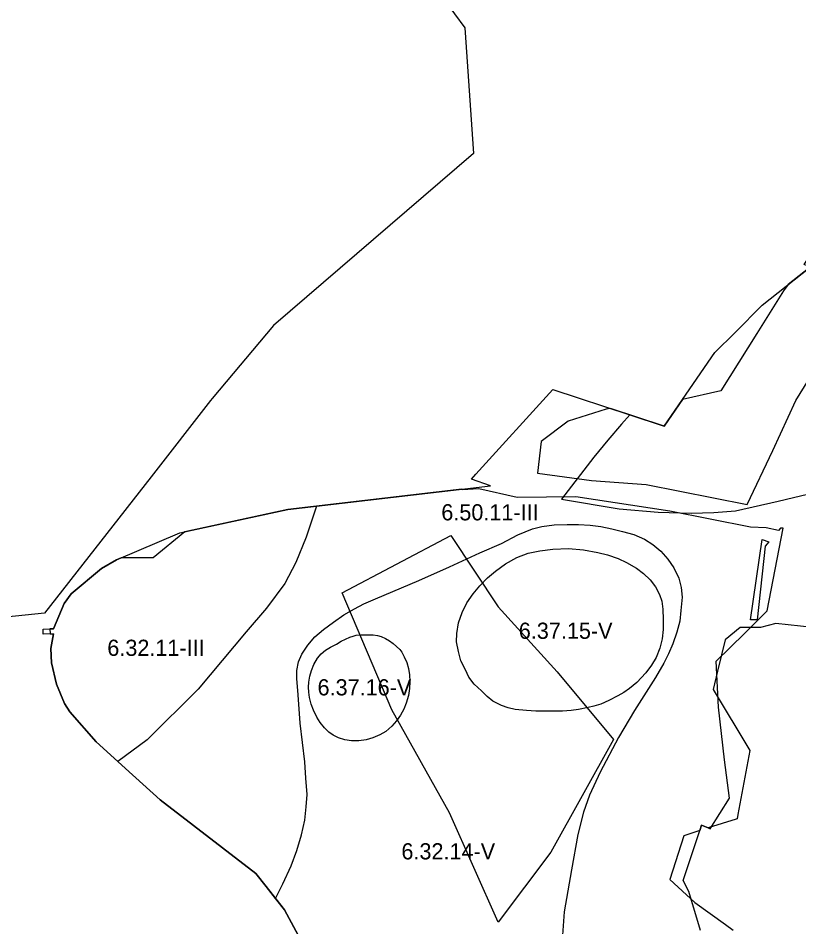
# Model space of a CAD drawing. Extents: x -555156 to -540209, y -1046851 to -1035695.
# Drawn here: x -545128 to -544645, y -1043130 to -1042568 of the extents above; entities that cross this region are included whole.
import ezdxf

# ---------------------------------------------------------------- set-up
doc = ezdxf.new("R2010")
doc.units = 0
for name, color, linetype in [('Vrstva 27', 7, 'Continuous'), ('Vrstva 28', 7, 'Continuous'), ('Vrstva 29', 7, 'Continuous')]:
    doc.layers.add(name, color=color, linetype=linetype)

msp = doc.modelspace()

# ---------------------------------------------------------------- linework, layer by layer
at = {"layer": 'Vrstva 28'}
for points in [[(-544870.74, -1042547.47), (-544851.56, -1042573.64), (-544846.21, -1042651.41), (-544969.84, -1042757.77), (-545007.86, -1042802.87), (-545008.88, -1042804.18), (-545045.53, -1042851.36), (-545111.56, -1042935.6), (-545207.45, -1042945.54)], [(-544749.41, -1042812.98), (-544728.08, -1042820), (-544696.84, -1042774.37), (-544684.33, -1042761.97), (-544667.45, -1042745.24), (-544637.87, -1042721.66), (-544641.52, -1042719.99), (-544638.13, -1042714.75), (-544623.97, -1042678.49), (-544607.13, -1042696.02), (-544598.1, -1042700.83), (-544587.56, -1042710.42), (-544566.83, -1042729.28), (-544565.67, -1042726.67), (-544561, -1042716.16), (-544566.52, -1042697.26), (-544567.8, -1042689.76), (-544554.69, -1042683.54), (-544543.88, -1042688.11), (-544522.03, -1042685.62), (-544507.06, -1042669.9), (-544495.63, -1042640.4), (-544502.76, -1042623.84), (-544501.01, -1042619.24)], [(-544943.16, -1042869.41), (-544835.67, -1042856.85), (-544847.39, -1042852.7), (-544844.58, -1042849.62), (-544796.95, -1042797.35), (-544749.41, -1042812.98)], [(-544749.41, -1042812.98), (-544754.57, -1042818.67), (-544763.05, -1042828.63), (-544771.74, -1042839.24), (-544791.66, -1042865.11), (-544756.05, -1042871.05), (-544731.89, -1042873.17), (-544711.55, -1042873.8), (-544697.35, -1042873.38), (-544683.94, -1042872.42), (-544657.66, -1042866.27), (-544634.35, -1042860.76), (-544615.49, -1042853.98), (-544602.35, -1042848.25), (-544591.33, -1042839.98), (-544566.3, -1042815.86)], [(-545066.08, -1043027.36), (-545079.6, -1043015.2), (-545095.79, -1042996.69), (-545099.06, -1042991.37), (-545104, -1042979.52), (-545107.11, -1042966.3), (-545107.57, -1042957.56), (-545106, -1042948.36), (-545112.42, -1042948.52), (-545112.22, -1042945.47), (-545105.95, -1042945.31), (-545099.33, -1042929.73), (-545094.94, -1042923.64), (-545076.31, -1042908.01), (-545066.87, -1042902.68), (-545027.83, -1042885.93), (-544961, -1042871.5), (-544943.16, -1042869.41)], [(-544943.16, -1042869.41), (-544949.53, -1042888.54)], [(-544968.58, -1043112.03), (-544964.08, -1043103.03), (-544959, -1043091.88), (-544955.36, -1043082.43), (-544952.46, -1043072.74), (-544950.52, -1043063.53), (-544949.55, -1043055.41), (-544949.07, -1043047.66), (-544949.73, -1043037.69), (-544950.44, -1043027.59), (-544953.35, -1043003.72), (-544954.56, -1042986.15), (-544955.41, -1042976.1), (-544955.41, -1042971.13), (-544954.32, -1042965.8), (-544952.38, -1042960.95), (-544948.63, -1042955.38), (-544944.27, -1042950.17), (-544938.82, -1042945.8), (-544932.64, -1042941.08), (-544926.34, -1042936.72), (-544919.8, -1042932.96), (-544913.87, -1042929.81), (-544906.79, -1042926.71), (-544879.88, -1042915.47), (-544861.02, -1042906.99), (-544842.15, -1042898.29), (-544828.8, -1042892.57), (-544818.63, -1042887.27), (-544809.63, -1042883.53), (-544803.81, -1042881.95), (-544796.18, -1042880.98), (-544788.19, -1042880.74), (-544781.17, -1042880.86)], [(-544781.17, -1042880.86), (-544774.02, -1042881.22), (-544767.24, -1042882.07), (-544760.58, -1042883.53), (-544753.92, -1042885.1), (-544746.89, -1042887.04), (-544740.35, -1042889.95), (-544735.15, -1042893.22), (-544730.3, -1042897.34), (-544725.82, -1042902.19), (-544722.19, -1042907.64), (-544719.04, -1042914.06), (-544717.59, -1042919.64), (-544717.1, -1042925.82), (-544717.83, -1042934.06), (-544718.55, -1042940.48), (-544720.37, -1042947.38), (-544722.79, -1042954.53), (-544725.46, -1042960.83), (-544728.28, -1042966.48), (-544733.58, -1042975.39), (-544746.51, -1042995.75), (-544756.47, -1043012.5), (-544767.7, -1043033.92), (-544774.27, -1043048.12), (-544778.09, -1043058.73), (-544781.48, -1043072.51), (-544785.56, -1043094.4), (-544790.01, -1043120.38), (-544791.86, -1043146.36)], [(-544949.53, -1042888.54), (-544956.1, -1042904.23), (-544962.88, -1042917.17), (-544974.12, -1042932.44), (-544986.73, -1042947.07), (-545016.4, -1042982.69), (-545047.92, -1043013.86), (-545066.08, -1043027.36)], [(-544778.09, -1042896.49), (-544769.25, -1042898.06), (-544763.2, -1042899.64), (-544756.66, -1042901.82), (-544751.45, -1042904.24), (-544745.27, -1042907.76), (-544740.91, -1042911.15), (-544736.92, -1042914.91), (-544733.53, -1042919.39), (-544731.1, -1042923.99), (-544729.65, -1042928.11), (-544729.05, -1042933.2), (-544728.68, -1042939.5), (-544728.68, -1042945.8), (-544729.41, -1042951.5), (-544730.74, -1042957.19), (-544733.16, -1042963.01), (-544735.95, -1042967.74), (-544739.58, -1042972.46), (-544745.03, -1042978.4), (-544749.63, -1042982.16), (-544753.16, -1042984.59), (-544756.9, -1042986.74), (-544762.37, -1042989.58), (-544767.28, -1042991.79), (-544771.57, -1042993.11), (-544775.17, -1042994.01), (-544781.12, -1042995.12), (-544785.76, -1042995.88), (-544790.95, -1042996.29), (-544795.58, -1042996.29), (-544801.74, -1042996.29), (-544807.63, -1042996.16), (-544813.37, -1042995.74), (-544820.29, -1042995.12), (-544824.72, -1042994.08), (-544828.87, -1042992.62), (-544834.13, -1042990.06), (-544837.73, -1042987.22), (-544841.07, -1042983.73), (-544845.67, -1042979.49), (-544849.06, -1042975.25), (-544851.12, -1042970.64), (-544853.91, -1042965.07), (-544855.48, -1042959.25), (-544856.69, -1042953.32), (-544856.33, -1042948.23), (-544855.48, -1042941.68), (-544853.06, -1042935.26), (-544850.27, -1042929.2), (-544846.28, -1042923.63), (-544842.16, -1042918.66), (-544837.44, -1042913.69), (-544832.59, -1042909.57), (-544826.29, -1042905.21), (-544819.27, -1042901.09), (-544812.25, -1042898.55), (-544805.1, -1042896.97), (-544796.99, -1042896)], [(-544796.99, -1042896), (-544787.3, -1042895.64), (-544778.09, -1042896.49)], [(-544636.15, -1042944.55), (-544659.01, -1042942.08), (-544668.58, -1042944.45), (-544671.05, -1042944.44), (-544681.14, -1042944.41), (-544690.43, -1042952.05), (-544695.13, -1042971.49), (-544697.87, -1042982.81), (-544675.26, -1043020.45), (-544682.56, -1043060.01), (-544683.06, -1043062.73), (-544683.59, -1043062.9), (-544700.95, -1043068.42), (-544704.96, -1043066.68), (-544706.1, -1043070.06), (-544715.99, -1043073.21), (-544724.67, -1043100.34), (-544709.2, -1043114.61), (-544690.23, -1043128.18), (-544685.48, -1043131.58)], [(-544889.23, -1042994.92), (-544891.23, -1042998.73), (-544893.66, -1043002.19), (-544896.56, -1043005.44), (-544900.3, -1043008.77), (-544903.97, -1043010.84), (-544908.4, -1043012.71), (-544912.55, -1043014.03), (-544917.12, -1043014.65), (-544921.55, -1043014.58), (-544925.7, -1043013.96), (-544929.64, -1043012.71), (-544932.89, -1043011.05), (-544935.59, -1043009.18), (-544938.29, -1043006.55), (-544940.99, -1043003.3), (-544943.07, -1042999.9), (-544945.01, -1042995.54), (-544946.53, -1042991.8), (-544947.5, -1042987.79), (-544948.05, -1042984.53), (-544948.26, -1042981.35), (-544948.05, -1042978.3), (-544947.43, -1042974.56), (-544946.32, -1042971.03), (-544944.87, -1042967.43), (-544942.65, -1042963.48), (-544940.44, -1042960.71), (-544937.6, -1042958.43), (-544934.62, -1042956.56), (-544930.89, -1042954.76), (-544927.99, -1042952.99), (-544925.38, -1042951.64), (-544922.53, -1042950.49), (-544920.6, -1042949.74), (-544918.62, -1042949.31), (-544915.81, -1042949.03), (-544913.2, -1042948.91), (-544911.03, -1042948.95)], [(-544911.03, -1042948.95), (-544908.22, -1042949.03), (-544905.41, -1042949.39), (-544903.28, -1042950.1), (-544900.51, -1042951.37), (-544898.17, -1042952.75), (-544895.88, -1042954.37), (-544893.71, -1042956.19), (-544891.73, -1042958.17), (-544890.54, -1042959.74), (-544888.95, -1042962.58), (-544887.43, -1042966.11), (-544886.39, -1042969.78), (-544885.77, -1042973.66), (-544885.56, -1042977.82), (-544885.63, -1042982.18), (-544886.32, -1042986.54), (-544887.77, -1042991.18), (-544889.23, -1042994.92)], [(-544968.58, -1043112.03), (-544972.91, -1043106.57), (-544974.42, -1043104.66), (-544980.8, -1043096.61), (-545039.89, -1043050.94), (-545061.34, -1043031.63), (-545066.08, -1043027.36)], [(-544792.29, -1043176.02), (-544835.62, -1043182.86), (-544865.45, -1043177.31), (-544872.71, -1043187.51), (-544874.75, -1043190.37), (-544892.34, -1043229.25), (-544902.88, -1043240.24), (-544913.74, -1043251.57), (-544916.19, -1043248.63), (-544910.49, -1043242.73), (-544911.76, -1043214.22), (-544963.02, -1043119.04), (-544968.58, -1043112.03)]]:
    msp.add_lwpolyline(points, dxfattribs=at)
at = {"layer": 'Vrstva 29'}
for points in [[(-544637.87, -1042721.66), (-544651.447734, -1042732.48363), (-544654.287903, -1042736.296021), (-544670.846008, -1042762.753906), (-544693.098999, -1042798.098999), (-544716.816971, -1042803.548912), (-544728.08, -1042820), (-544761.261256, -1042809.087332), (-544764.135986, -1042809.39801), (-544787.56897, -1042816.843018), (-544804.348022, -1042829.513), (-544806.448975, -1042848.942017), (-544773.192017, -1042853.655029), (-544739.213013, -1042856.143005), (-544676.805908, -1042868.490906), (-544660.865906, -1042835.091003), (-544646.684021, -1042804.072021), (-544629.5, -1042776.398987)], [(-544853.398155, -1042858.922269), (-544961, -1042871.5), (-545024.764195, -1042885.268028), (-545044.302002, -1042901.377014), (-545063.987182, -1042901.443135), (-545066.87, -1042902.68), (-545076.31, -1042908.01), (-545094.94, -1042923.64), (-545099.33, -1042929.73), (-545105.95, -1042945.31), (-545108.185501, -1042945.367046), (-545108.07433, -1042948.411697), (-545106, -1042948.36), (-545107.57, -1042957.56), (-545107.11, -1042966.3), (-545104, -1042979.52), (-545099.06, -1042991.37), (-545095.79, -1042996.69), (-545079.6, -1043015.2), (-545061.34, -1043031.63), (-545039.89, -1043050.94), (-544980.8, -1043096.61), (-544974.42, -1043104.66), (-544972.91, -1043106.57), (-544963.02, -1043119.04), (-544919.57813, -1043199.70323)], [(-544705.659912, -1043131.882019), (-544712.825598, -1043107.795863), (-544716.5, -1043100.89), (-544706.1, -1043070.06), (-544704.96, -1043066.68), (-544700.95, -1043068.42), (-544699.647633, -1043068.984717), (-544687.666016, -1043049.984985), (-544690.770996, -1043026.234009), (-544694.578979, -1042993.747986), (-544695.963013, -1042965.317017), (-544678.499023, -1042948.124023), (-544664.406982, -1042934.177002), (-544654.448975, -1042883.122986), (-544656.191811, -1042883.065218), (-544657.48, -1042884.58), (-544665.1, -1042882.8), (-544665.091107, -1042882.770241), (-544674.812988, -1042882.447998), (-544724.687988, -1042872.575012), (-544782.828003, -1042863.695007), (-544819.119019, -1042864.044983), (-544842.812012, -1042858.640015), (-544853.135986, -1042859.257996), (-544853.398155, -1042858.922269)], [(-544830.914001, -1042931.747986), (-544794.390015, -1042971.955017), (-544759.552002, -1043013.786011), (-544798.348022, -1043083.492981), (-544830.804016, -1043126.783997), (-544860.892029, -1043059.150024), (-544896.701904, -1042995.302002), (-544927.369995, -1042923.023987), (-544860.174011, -1042887.646912), (-544830.914001, -1042931.747986)], [(-544670.55, -1042939.81), (-544674.76, -1042939.8), (-544667.49, -1042890.16), (-544663.39, -1042891.53), (-544665.66, -1042894.2), (-544670.55, -1042939.81)]]:
    msp.add_lwpolyline(points, dxfattribs=at)

# ---------------------------------------------------------------- texts
at = {"layer": 'Vrstva 27'}
for s, p in [('6.50.11-III', (-544866.016548, -1042878.24)), ('6.37.15-V', (-544818.086558, -1042951.48)), ('6.32.11-III', (-545072.636548, -1042962.02)), ('6.37.16-V', (-544942.587974, -1042986.47)), ('6.32.14-V', (-544890.690884, -1043087.87))]:
    msp.add_text(s, height=10, dxfattribs=at).set_placement(p)

doc.saveas('drawing.dxf')
